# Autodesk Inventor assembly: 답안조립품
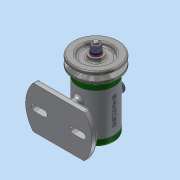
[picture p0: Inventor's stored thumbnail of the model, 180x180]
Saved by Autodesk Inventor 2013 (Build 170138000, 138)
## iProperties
Created: 2017-12
Part Number: 답안조립품
Document SubType Name: Assembly
Designer: Administrator
Author: Administrator
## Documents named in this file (14)
- C:\Users\Administrator\Desktop\471208V1016\답안조립품.iam
- C:\Users\Administrator\Desktop\471208V1016\V벨트풀리.ipt
- C:\Users\Administrator\Desktop\471208V1016\고무캡.ipt
- C:\Users\Administrator\Desktop\471208V1016\너트 M 8.ipt
- C:\Users\Administrator\Desktop\471208V1016\뒤커버.ipt
- C:\Users\Administrator\Desktop\471208V1016\베어링 15 x 32 x 9.ipt
- C:\Users\Administrator\Desktop\471208V1016\본체.ipt
- C:\Users\Administrator\Desktop\471208V1016\볼트 M4 x 12.ipt
- C:\Users\Administrator\Desktop\471208V1016\스프링와셔 8.ipt
- C:\Users\Administrator\Desktop\471208V1016\앞커버.ipt
- C:\Users\Administrator\Desktop\471208V1016\오일 실 15 25 7.ipt
- C:\Users\Administrator\Desktop\471208V1016\와셔 8x17.ipt
- C:\Users\Administrator\Desktop\471208V1016\축.ipt
- C:\Users\Administrator\Desktop\471208V1016\키 3 x 3 x 12.ipt
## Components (2 placed, 2 different names)
1. V벨트풀리:1
2. 고무캡:1
